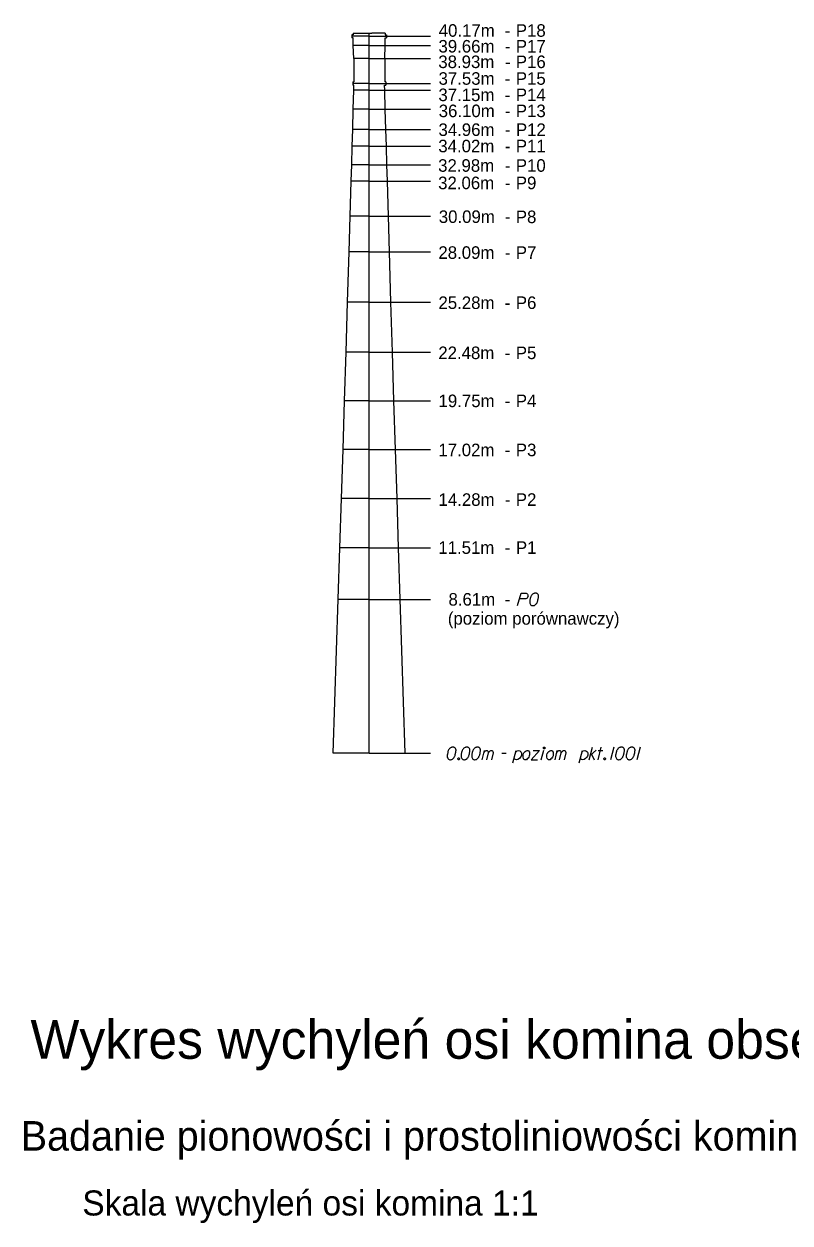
# Model space of a CAD drawing. Extents: x 138 to 264, y -75 to 121.
# Drawn here: x 198.02 to 207.43, y 84.56 to 99.29 of the extents above; entities that cross this region are included whole.
import ezdxf

# ---------------------------------------------------------------- set-up
doc = ezdxf.new("R2010")
doc.units = 0
doc.layers.add('Opisy', color=7, linetype='Continuous')

msp = doc.modelspace()

# ---------------------------------------------------------------- linework, layer by layer
at = {"layer": 'Opisy'}
for p, q in [((202.049, 99.16), (202.049, 99.141)), ((202.066, 99.16), (202.049, 99.16)), ((202.066, 99.178), (202.066, 99.16)), ((202.066, 99.178), (202.293, 99.178)), ((202.262, 90.332), (202.262, 99.178)), ((202.458, 99.178), (202.293, 99.178)), ((202.458, 99.178), (202.458, 99.16)), ((202.458, 99.16), (202.475, 99.16)), ((202.475, 99.16), (202.475, 99.141)), ((202.262, 99.141), (202.049, 99.141)), ((202.049, 99.141), (202.049, 99.122)), ((202.066, 99.122), (202.049, 99.122)), ((202.066, 99.028), (202.066, 99.122)), ((202.262, 99.028), (202.066, 99.028)), ((202.072, 98.868), (202.066, 99.028)), ((202.262, 99.141), (203.015, 99.141)), ((202.262, 99.028), (203.015, 99.028)), ((202.452, 98.868), (202.458, 99.028)), ((202.458, 99.122), (202.475, 99.122)), ((202.458, 99.028), (202.458, 99.122)), ((202.475, 99.141), (202.475, 99.122)), ((202.262, 98.868), (202.072, 98.868)), ((202.072, 98.868), (202.072, 98.58)), ((202.262, 98.868), (203.015, 98.868)), ((202.452, 98.868), (202.452, 98.58)), ((202.059, 98.58), (202.059, 98.561)), ((202.059, 98.58), (202.072, 98.58)), ((202.465, 98.58), (202.452, 98.58)), ((202.465, 98.58), (202.465, 98.561)), ((202.262, 98.561), (202.059, 98.561)), ((202.059, 98.561), (202.059, 98.542)), ((202.074, 98.542), (202.059, 98.542)), ((202.066, 98.247), (202.072, 98.478)), ((202.072, 98.478), (202.074, 98.542)), ((202.262, 98.478), (202.072, 98.478)), ((202.262, 98.561), (203.015, 98.561)), ((202.262, 98.478), (203.015, 98.478)), ((202.452, 98.478), (202.45, 98.542)), ((202.45, 98.542), (202.465, 98.542)), ((202.458, 98.247), (202.452, 98.478)), ((202.465, 98.561), (202.465, 98.542)), ((202.059, 97.997), (202.066, 98.247)), ((202.262, 98.247), (202.066, 98.247)), ((202.262, 98.247), (203.015, 98.247)), ((202.465, 97.997), (202.458, 98.247)), ((202.053, 97.791), (202.059, 97.997)), ((202.262, 97.997), (202.059, 97.997)), ((202.262, 97.997), (203.015, 97.997)), ((202.472, 97.791), (202.465, 97.997)), ((202.047, 97.563), (202.053, 97.791)), ((202.262, 97.791), (202.053, 97.791)), ((202.262, 97.791), (203.015, 97.791)), ((202.477, 97.563), (202.472, 97.791)), ((202.04, 97.361), (202.047, 97.563)), ((202.262, 97.563), (202.047, 97.563)), ((202.262, 97.563), (203.015, 97.563)), ((202.485, 97.361), (202.477, 97.563)), ((202.028, 96.929), (202.04, 97.361)), ((202.262, 97.361), (202.04, 97.361)), ((202.262, 97.361), (203.015, 97.361)), ((202.497, 96.929), (202.485, 97.361)), ((202.014, 96.491), (202.028, 96.929)), ((202.262, 96.929), (202.028, 96.929)), ((202.262, 96.929), (203.015, 96.929)), ((202.51, 96.491), (202.497, 96.929)), ((201.997, 95.874), (202.014, 96.491)), ((202.262, 96.491), (202.014, 96.491)), ((202.262, 96.491), (203.015, 96.491)), ((202.527, 95.874), (202.51, 96.491)), ((201.977, 95.261), (201.997, 95.874)), ((202.262, 95.874), (201.997, 95.874)), ((202.262, 95.874), (203.015, 95.874)), ((202.547, 95.261), (202.527, 95.874)), ((201.958, 94.662), (201.977, 95.261)), ((202.262, 95.261), (201.977, 95.261)), ((202.262, 95.261), (203.015, 95.261)), ((202.566, 94.662), (202.547, 95.261)), ((201.94, 94.064), (201.958, 94.662)), ((202.262, 94.662), (201.958, 94.662)), ((202.262, 94.662), (203.015, 94.662)), ((202.584, 94.064), (202.566, 94.662)), ((201.921, 93.462), (201.94, 94.064)), ((202.262, 94.064), (201.94, 94.064)), ((202.262, 94.064), (203.015, 94.064)), ((202.603, 93.462), (202.584, 94.064)), ((201.901, 92.856), (201.921, 93.462)), ((202.262, 93.462), (201.921, 93.462)), ((202.262, 93.462), (203.015, 93.462)), ((202.623, 92.856), (202.603, 93.462)), ((201.819, 90.332), (201.901, 92.856)), ((202.262, 92.856), (201.901, 92.856)), ((202.262, 92.856), (203.015, 92.856)), ((202.705, 90.332), (202.623, 92.856)), ((202.262, 92.219), (201.881, 92.219)), ((202.262, 92.219), (203.015, 92.219)), ((202.262, 90.332), (201.819, 90.332)), ((202.262, 90.332), (203.015, 90.332))]:
    msp.add_line(p, q, dxfattribs=at)
for points in [[(204.084, 92.145), (204.126, 92.299), (204.178, 92.299), (204.185, 92.298), (204.189, 92.296), (204.196, 92.293), (204.201, 92.289), (204.205, 92.284), (204.208, 92.278), (204.211, 92.27), (204.212, 92.262), (204.211, 92.256), (204.209, 92.251), (204.207, 92.247), (204.205, 92.243), (204.201, 92.238), (204.196, 92.234), (204.192, 92.232), (204.186, 92.23), (204.18, 92.228), (204.107, 92.228)], [(204.305, 92.299), (204.303, 92.299), (204.296, 92.298), (204.291, 92.296), (204.287, 92.295), (204.281, 92.293), (204.274, 92.289), (204.268, 92.285), (204.262, 92.281), (204.258, 92.276), (204.254, 92.27), (204.251, 92.264), (204.247, 92.256), (204.245, 92.251), (204.242, 92.244), (204.239, 92.232), (204.235, 92.214), (204.232, 92.199), (204.232, 92.186), (204.234, 92.176), (204.239, 92.165), (204.242, 92.159), (204.248, 92.152), (204.256, 92.147), (204.259, 92.146), (204.266, 92.145), (204.273, 92.145), (204.282, 92.146), (204.291, 92.148), (204.297, 92.152), (204.305, 92.158), (204.309, 92.162), (204.314, 92.166), (204.317, 92.171), (204.32, 92.175), (204.322, 92.181), (204.324, 92.183), (204.326, 92.19), (204.328, 92.197), (204.331, 92.204), (204.332, 92.209), (204.333, 92.213), (204.334, 92.217), (204.337, 92.228), (204.338, 92.234), (204.339, 92.24), (204.341, 92.249), (204.342, 92.26), (204.342, 92.264), (204.341, 92.268), (204.339, 92.273), (204.336, 92.281), (204.332, 92.285), (204.328, 92.289), (204.324, 92.293), (204.319, 92.295), (204.315, 92.296), (204.311, 92.298), (204.305, 92.299)], [(203.291, 90.406), (203.289, 90.406), (203.282, 90.405), (203.277, 90.404), (203.273, 90.403), (203.267, 90.4), (203.26, 90.397), (203.254, 90.393), (203.248, 90.388), (203.244, 90.383), (203.24, 90.377), (203.237, 90.371), (203.233, 90.364), (203.231, 90.359), (203.228, 90.352), (203.225, 90.34), (203.221, 90.321), (203.219, 90.307), (203.219, 90.293), (203.22, 90.284), (203.225, 90.273), (203.228, 90.267), (203.234, 90.259), (203.242, 90.255), (203.245, 90.253), (203.253, 90.252), (203.259, 90.252), (203.268, 90.253), (203.277, 90.256), (203.283, 90.259), (203.291, 90.266), (203.295, 90.269), (203.3, 90.274), (203.304, 90.279), (203.306, 90.283), (203.308, 90.289), (203.31, 90.291), (203.312, 90.297), (203.315, 90.304), (203.317, 90.312), (203.318, 90.317), (203.319, 90.32), (203.321, 90.325), (203.323, 90.336), (203.324, 90.342), (203.325, 90.348), (203.327, 90.357), (203.328, 90.367), (203.328, 90.371), (203.327, 90.376), (203.325, 90.381), (203.322, 90.388), (203.318, 90.393), (203.315, 90.397), (203.31, 90.4), (203.305, 90.403), (203.301, 90.404), (203.298, 90.405), (203.291, 90.406)], [(203.463, 90.406), (203.46, 90.406), (203.453, 90.405), (203.448, 90.404), (203.444, 90.403), (203.438, 90.4), (203.431, 90.397), (203.425, 90.393), (203.419, 90.388), (203.415, 90.383), (203.412, 90.377), (203.408, 90.371), (203.404, 90.364), (203.402, 90.359), (203.399, 90.352), (203.396, 90.34), (203.392, 90.321), (203.39, 90.307), (203.39, 90.293), (203.391, 90.284), (203.396, 90.273), (203.399, 90.267), (203.406, 90.259), (203.413, 90.255), (203.416, 90.253), (203.424, 90.252), (203.43, 90.252), (203.44, 90.253), (203.448, 90.256), (203.454, 90.259), (203.463, 90.266), (203.466, 90.269), (203.471, 90.274), (203.475, 90.279), (203.477, 90.283), (203.48, 90.289), (203.481, 90.291), (203.483, 90.297), (203.486, 90.304), (203.488, 90.312), (203.489, 90.317), (203.491, 90.32), (203.492, 90.325), (203.494, 90.336), (203.495, 90.342), (203.497, 90.348), (203.498, 90.357), (203.499, 90.367), (203.499, 90.371), (203.498, 90.376), (203.497, 90.381), (203.493, 90.388), (203.489, 90.393), (203.486, 90.397), (203.481, 90.4), (203.476, 90.403), (203.472, 90.404), (203.469, 90.405), (203.463, 90.406)], [(203.592, 90.406), (203.59, 90.406), (203.583, 90.405), (203.578, 90.404), (203.574, 90.403), (203.568, 90.4), (203.561, 90.397), (203.555, 90.393), (203.549, 90.388), (203.545, 90.383), (203.541, 90.377), (203.538, 90.371), (203.534, 90.364), (203.532, 90.359), (203.529, 90.352), (203.526, 90.34), (203.522, 90.321), (203.52, 90.307), (203.52, 90.293), (203.521, 90.284), (203.526, 90.273), (203.529, 90.267), (203.535, 90.259), (203.543, 90.255), (203.546, 90.253), (203.554, 90.252), (203.56, 90.252), (203.569, 90.253), (203.578, 90.256), (203.584, 90.259), (203.592, 90.266), (203.596, 90.269), (203.601, 90.274), (203.605, 90.279), (203.607, 90.283), (203.609, 90.289), (203.611, 90.291), (203.613, 90.297), (203.616, 90.304), (203.618, 90.312), (203.619, 90.317), (203.62, 90.32), (203.622, 90.325), (203.624, 90.336), (203.625, 90.342), (203.626, 90.348), (203.628, 90.357), (203.629, 90.367), (203.629, 90.371), (203.628, 90.376), (203.626, 90.381), (203.623, 90.388), (203.619, 90.393), (203.616, 90.397), (203.611, 90.4), (203.606, 90.403), (203.602, 90.404), (203.599, 90.405), (203.592, 90.406)], [(203.649, 90.252), (203.677, 90.363)], [(203.67, 90.333), (203.676, 90.347), (203.682, 90.354), (203.69, 90.359), (203.697, 90.363), (203.702, 90.365), (203.709, 90.365), (203.711, 90.364), (203.716, 90.359), (203.721, 90.353), (203.725, 90.342), (203.726, 90.336), (203.732, 90.347), (203.739, 90.354), (203.747, 90.359), (203.754, 90.363), (203.76, 90.365), (203.766, 90.365), (203.771, 90.364), (203.775, 90.359), (203.778, 90.353), (203.782, 90.342), (203.783, 90.336), (203.762, 90.252)], [(203.705, 90.252), (203.726, 90.336)], [(203.892, 90.33), (203.945, 90.33)], [(204.027, 90.212), (204.068, 90.364)], [(204.065, 90.35), (204.077, 90.36), (204.095, 90.364), (204.11, 90.361), (204.119, 90.354), (204.127, 90.344), (204.132, 90.331), (204.133, 90.319), (204.13, 90.308), (204.127, 90.295), (204.117, 90.28), (204.105, 90.267), (204.087, 90.255), (204.071, 90.252), (204.056, 90.253), (204.04, 90.262)], [(204.201, 90.364), (204.209, 90.364), (204.219, 90.359), (204.229, 90.346), (204.23, 90.34), (204.231, 90.333), (204.231, 90.329), (204.231, 90.31), (204.227, 90.298), (204.221, 90.284), (204.214, 90.272), (204.202, 90.261), (204.191, 90.252), (204.173, 90.252), (204.166, 90.255), (204.158, 90.261), (204.155, 90.267), (204.15, 90.281), (204.15, 90.303), (204.152, 90.31), (204.157, 90.326), (204.162, 90.335), (204.164, 90.34), (204.176, 90.353), (204.189, 90.36), (204.201, 90.364)], [(204.274, 90.366), (204.352, 90.366), (204.252, 90.252), (204.329, 90.252)], [(204.373, 90.252), (204.405, 90.37)], [(204.407, 90.406), (204.413, 90.406), (204.417, 90.404), (204.42, 90.399), (204.42, 90.393), (204.417, 90.388), (204.413, 90.386), (204.407, 90.386), (204.403, 90.388), (204.4, 90.393), (204.4, 90.399), (204.403, 90.404), (204.407, 90.406)], [(204.492, 90.364), (204.501, 90.364), (204.51, 90.359), (204.52, 90.346), (204.521, 90.34), (204.522, 90.333), (204.522, 90.329), (204.522, 90.31), (204.519, 90.298), (204.513, 90.284), (204.505, 90.272), (204.493, 90.261), (204.482, 90.252), (204.464, 90.252), (204.457, 90.255), (204.45, 90.261), (204.446, 90.267), (204.441, 90.281), (204.441, 90.303), (204.443, 90.31), (204.448, 90.326), (204.453, 90.335), (204.456, 90.34), (204.468, 90.353), (204.48, 90.36), (204.492, 90.364)], [(204.543, 90.252), (204.571, 90.363)], [(204.564, 90.333), (204.57, 90.347), (204.576, 90.354), (204.583, 90.359), (204.59, 90.363), (204.595, 90.365), (204.602, 90.365), (204.605, 90.364), (204.61, 90.359), (204.615, 90.353), (204.618, 90.342), (204.619, 90.336), (204.626, 90.347), (204.633, 90.354), (204.64, 90.359), (204.647, 90.363), (204.653, 90.365), (204.66, 90.365), (204.664, 90.364), (204.668, 90.359), (204.672, 90.353), (204.675, 90.342), (204.677, 90.336), (204.656, 90.252)], [(204.599, 90.252), (204.619, 90.336)], [(204.84, 90.212), (204.882, 90.364)], [(204.878, 90.35), (204.89, 90.36), (204.908, 90.364), (204.923, 90.361), (204.933, 90.354), (204.94, 90.344), (204.945, 90.331), (204.946, 90.319), (204.944, 90.308), (204.94, 90.295), (204.93, 90.28), (204.918, 90.267), (204.9, 90.255), (204.884, 90.252), (204.87, 90.253), (204.854, 90.262)], [(204.963, 90.252), (205.004, 90.406)], [(204.978, 90.307), (205.05, 90.367)], [(204.992, 90.319), (205.024, 90.252)], [(205.071, 90.252), (205.111, 90.406)], [(205.071, 90.364), (205.129, 90.364)], [(205.266, 90.406), (205.225, 90.252)], [(205.36, 90.406), (205.357, 90.406), (205.35, 90.405), (205.345, 90.404), (205.342, 90.403), (205.336, 90.4), (205.328, 90.397), (205.322, 90.393), (205.316, 90.388), (205.313, 90.383), (205.309, 90.377), (205.305, 90.371), (205.302, 90.364), (205.299, 90.359), (205.297, 90.352), (205.293, 90.34), (205.29, 90.321), (205.287, 90.307), (205.287, 90.293), (205.288, 90.284), (205.293, 90.273), (205.297, 90.267), (205.303, 90.259), (205.31, 90.255), (205.314, 90.253), (205.321, 90.252), (205.327, 90.252), (205.337, 90.253), (205.345, 90.256), (205.351, 90.259), (205.36, 90.266), (205.364, 90.269), (205.368, 90.274), (205.372, 90.279), (205.374, 90.283), (205.377, 90.289), (205.378, 90.291), (205.381, 90.297), (205.383, 90.304), (205.385, 90.312), (205.387, 90.317), (205.388, 90.32), (205.389, 90.325), (205.391, 90.336), (205.393, 90.342), (205.394, 90.348), (205.395, 90.357), (205.396, 90.367), (205.396, 90.371), (205.395, 90.376), (205.394, 90.381), (205.39, 90.388), (205.387, 90.393), (205.383, 90.397), (205.378, 90.4), (205.373, 90.403), (205.37, 90.404), (205.366, 90.405), (205.36, 90.406)], [(205.49, 90.406), (205.487, 90.406), (205.48, 90.405), (205.475, 90.404), (205.472, 90.403), (205.465, 90.4), (205.458, 90.397), (205.452, 90.393), (205.446, 90.388), (205.442, 90.383), (205.439, 90.377), (205.435, 90.371), (205.432, 90.364), (205.429, 90.359), (205.427, 90.352), (205.423, 90.34), (205.419, 90.321), (205.417, 90.307), (205.417, 90.293), (205.418, 90.284), (205.423, 90.273), (205.427, 90.267), (205.433, 90.259), (205.44, 90.255), (205.444, 90.253), (205.451, 90.252), (205.457, 90.252), (205.467, 90.253), (205.475, 90.256), (205.481, 90.259), (205.49, 90.266), (205.493, 90.269), (205.498, 90.274), (205.502, 90.279), (205.504, 90.283), (205.507, 90.289), (205.508, 90.291), (205.51, 90.297), (205.513, 90.304), (205.515, 90.312), (205.516, 90.317), (205.518, 90.32), (205.519, 90.325), (205.521, 90.336), (205.523, 90.342), (205.524, 90.348), (205.525, 90.357), (205.526, 90.367), (205.526, 90.371), (205.525, 90.376), (205.524, 90.381), (205.52, 90.388), (205.516, 90.393), (205.513, 90.397), (205.508, 90.4), (205.503, 90.403), (205.499, 90.404), (205.496, 90.405), (205.49, 90.406)], [(205.588, 90.406), (205.547, 90.252)], [(203.356, 90.273), (203.362, 90.273), (203.365, 90.27), (203.369, 90.266), (203.369, 90.259), (203.365, 90.255), (203.362, 90.252), (203.356, 90.252), (203.352, 90.255), (203.348, 90.259), (203.348, 90.266), (203.352, 90.27), (203.356, 90.273)], [(205.15, 90.273), (205.156, 90.273), (205.16, 90.27), (205.163, 90.266), (205.163, 90.259), (205.16, 90.255), (205.156, 90.252), (205.15, 90.252), (205.146, 90.255), (205.143, 90.259), (205.143, 90.266), (205.146, 90.27), (205.15, 90.273)]]:
    msp.add_lwpolyline(points, dxfattribs=at)

# ---------------------------------------------------------------- texts
for s, height, p in [('40.17m', 0.1542, (203.115, 99.135)), ('-', 0.154, (203.925, 99.135)), ('P18', 0.1542, (204.062, 99.135)), ('39.66m', 0.1542, (203.112, 98.941)), ('-', 0.154, (203.927, 98.941)), ('P17', 0.1542, (204.062, 98.941)), ('38.93m', 0.1542, (203.11, 98.75)), ('P16', 0.1542, (204.062, 98.75)), ('-', 0.154, (203.929, 98.75)), ('37.53m', 0.1542, (203.113, 98.545)), ('-', 0.154, (203.925, 98.545)), ('P15', 0.1542, (204.062, 98.545)), ('37.15m', 0.1542, (203.111, 98.344)), ('P14', 0.1542, (204.062, 98.344)), ('36.10m', 0.1542, (203.115, 98.147)), ('-', 0.154, (203.925, 98.344)), ('P13', 0.1542, (204.062, 98.147)), ('-', 0.154, (203.927, 98.147)), ('34.96m', 0.1542, (203.112, 97.916)), ('-', 0.154, (203.927, 97.916)), ('P12', 0.1542, (204.063, 97.916)), ('34.02m', 0.1542, (203.11, 97.715)), ('P11', 0.1542, (204.062, 97.715)), ('-', 0.154, (203.927, 97.715)), ('32.98m', 0.1542, (203.108, 97.476)), ('-', 0.154, (203.927, 97.476)), ('P10', 0.1542, (204.062, 97.476)), ('32.06m', 0.1542, (203.108, 97.262)), ('P9', 0.1542, (204.062, 97.262)), ('-', 0.154, (203.927, 97.262)), ('30.09m', 0.1542, (203.116, 96.847)), ('P8', 0.1542, (204.062, 96.845)), ('-', 0.154, (203.927, 96.847)), ('28.09m', 0.1542, (203.111, 96.406)), ('P7', 0.1542, (204.062, 96.406)), ('-', 0.154, (203.927, 96.406)), ('25.28m', 0.1542, (203.112, 95.79)), ('P6', 0.1542, (204.062, 95.79)), ('-', 0.154, (203.925, 95.79)), ('22.48m', 0.1542, (203.11, 95.174)), ('P5', 0.1542, (204.062, 95.174)), ('-', 0.154, (203.925, 95.174)), ('19.75m', 0.1542, (203.113, 94.584)), ('P4', 0.1542, (204.062, 94.584)), ('-', 0.154, (203.925, 94.584)), ('17.02m', 0.1542, (203.111, 93.981)), ('-', 0.154, (203.925, 93.981)), ('P3', 0.1542, (204.062, 93.981)), ('14.28m', 0.1542, (203.113, 93.371)), ('-', 0.154, (203.926, 93.371)), ('P2', 0.1542, (204.062, 93.371)), ('11.51m', 0.1542, (203.11, 92.781)), ('-', 0.154, (203.925, 92.781)), ('P1', 0.1542, (204.063, 92.781)), ('8.61m', 0.1542, (203.235, 92.145)), ('-', 0.154, (203.925, 92.145)), ('(poziom porównawczy)', 0.15416, (203.227, 91.911)), ('Wykres wychyleń osi komina obserwowanych ze stanowiska 1001', 0.47516, (198.103, 86.577)), ('Badanie pionowości i prostoliniowości komina zakładu ceramicznego "Ceramika Stróże"', 0.36281, (197.983, 85.448)), ('Skala wychyleń osi komina 1:1', 0.30766, (198.739, 84.651))]:
    msp.add_text(s, height=height, dxfattribs=at).set_placement(p)

doc.saveas('drawing.dxf')
